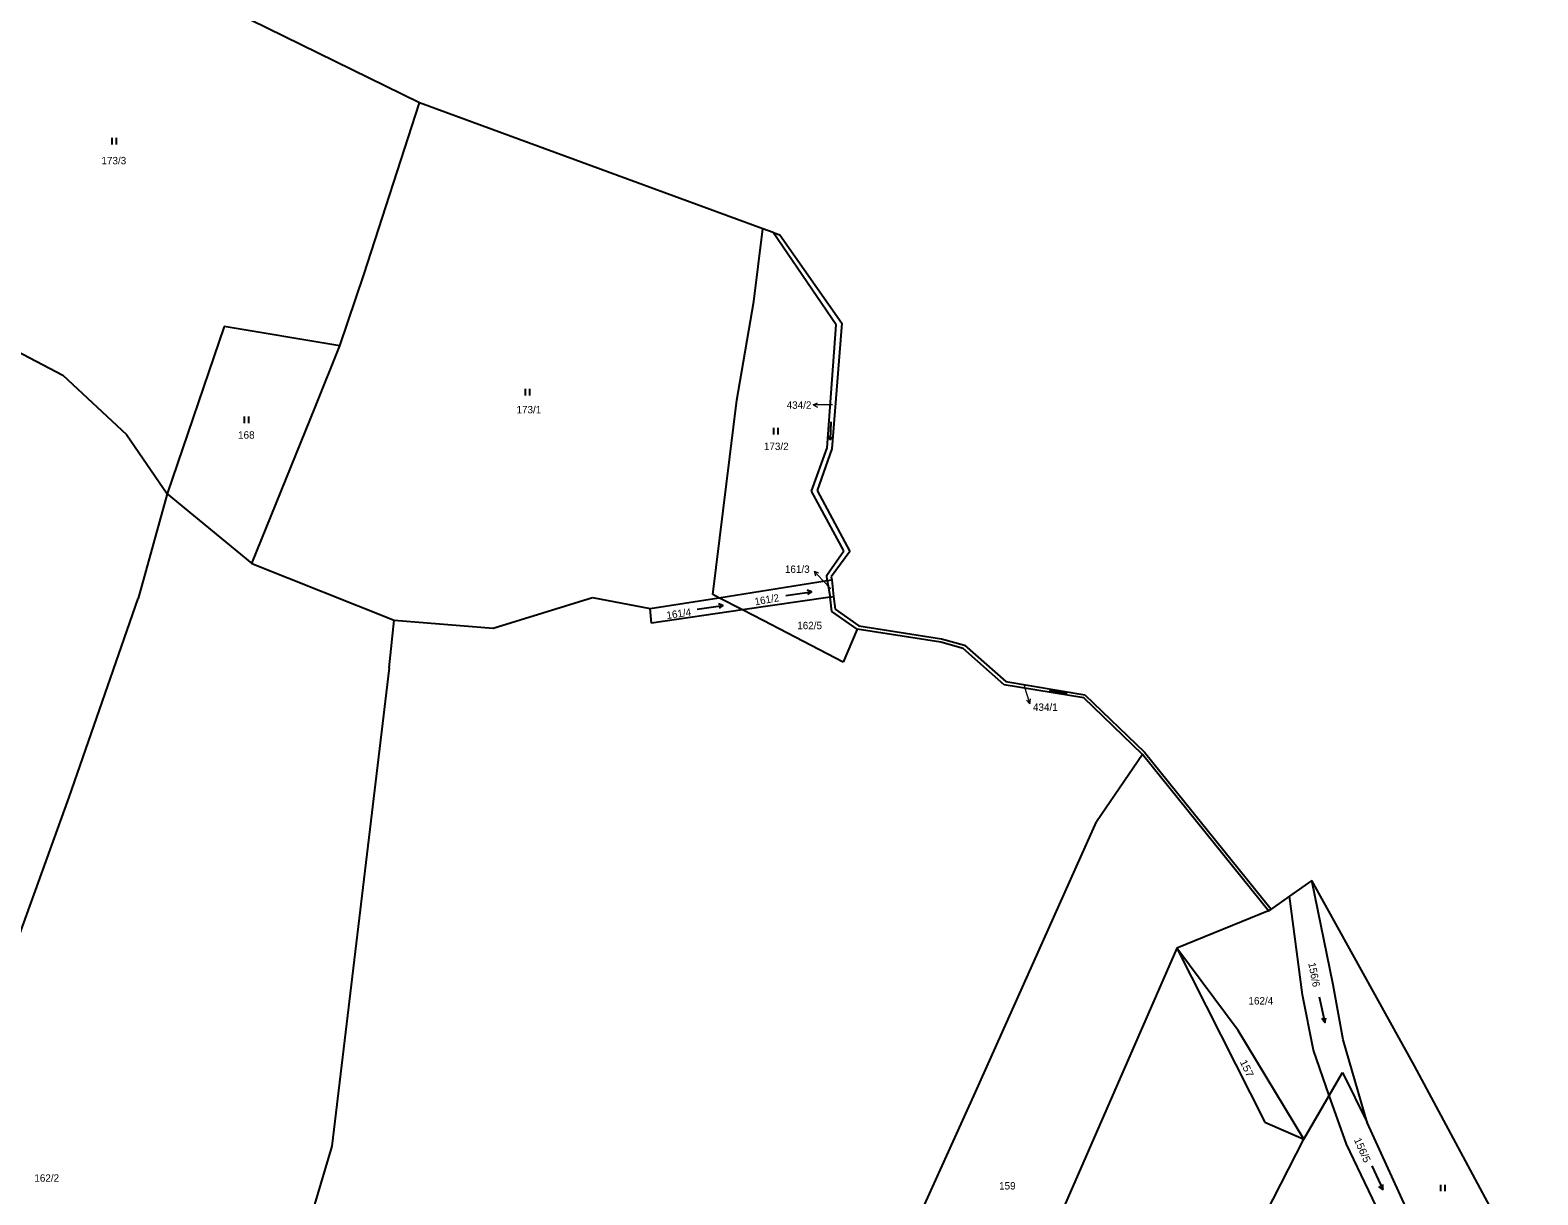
# Model space of a CAD drawing. Extents: x -791548 to -789311, y -1142631 to -1140855.
# Drawn here: x -790140.3 to -789793.9, y -1141655.6 to -1141388.1 of the extents above; entities that cross this region are included whole.
import ezdxf
from ezdxf.enums import TextEntityAlignment as Align

# ---------------------------------------------------------------- set-up
doc = ezdxf.new("R2010")
doc.units = 0
doc.header["$LTSCALE"] = 0.68
for name, color, linetype, lineweight in [('1', 7, 'Continuous', 25), ('3', 7, 'Continuous', 25), ('7', 7, 'Continuous', 13)]:
    doc.layers.add(name, color=color, linetype=linetype, lineweight=lineweight)
doc.layers.add('2', color=7, linetype='Continuous')

msp = doc.modelspace()

# ---------------------------------------------------------------- linework, layer by layer
at = {"layer": '1'}
for p, q in [((-790050.91, -1141404.77), (-790097.47, -1141381.98)), ((-790063.68, -1141444.29), (-790050.91, -1141404.77)), ((-789972, -1141433.72), (-790050.91, -1141404.77)), ((-789974.08, -1141450.41), (-789972, -1141433.72)), ((-789969.65, -1141434.59), (-789972, -1141433.72)), ((-789969.65, -1141434.59), (-789968.14, -1141435.11)), ((-789955.16, -1141455.79), (-789969.65, -1141434.59)), ((-789968.14, -1141435.11), (-789953.89, -1141455.4)), ((-790069.2, -1141460.63), (-790063.68, -1141444.29)), ((-789977.98, -1141473.06), (-789974.08, -1141450.41)), ((-790154.9, -1141455.81), (-790132.85, -1141467.37)), ((-790095.79, -1141456.13), (-790108.83, -1141494.58)), ((-790069.2, -1141460.63), (-790095.79, -1141456.13)), ((-789957.25, -1141484.05), (-789955.16, -1141455.79)), ((-789953.89, -1141455.4), (-789956.14, -1141484.29)), ((-790074.81, -1141474.52), (-790069.2, -1141460.63)), ((-790132.85, -1141467.37), (-790118.23, -1141480.98)), ((-790089.42, -1141510.57), (-790074.81, -1141474.52)), ((-789983.5, -1141517.74), (-789977.98, -1141473.06)), ((-790118.23, -1141480.98), (-790108.83, -1141494.58)), ((-789960.79, -1141493.95), (-789957.25, -1141484.05)), ((-789956.14, -1141484.29), (-789959.54, -1141493.85)), ((-790108.83, -1141494.58), (-790115.53, -1141518.63)), ((-790108.83, -1141494.58), (-790089.42, -1141510.57)), ((-789953.37, -1141507.66), (-789960.79, -1141493.95)), ((-789959.54, -1141493.85), (-789952.02, -1141507.86)), ((-789957.33, -1141513.28), (-789953.37, -1141507.66)), ((-789952.02, -1141507.86), (-789956.28, -1141513.62)), ((-790089.42, -1141510.57), (-790056.74, -1141523.64)), ((-789982.13, -1141518.45), (-789957.23, -1141514.48)), ((-789957.23, -1141514.48), (-789957.33, -1141513.28)), ((-789957.23, -1141514.48), (-789956.19, -1141514.36)), ((-789957.23, -1141514.48), (-789956.56, -1141518.29)), ((-789956.28, -1141513.62), (-789956.19, -1141514.36)), ((-789956.19, -1141514.36), (-789955.74, -1141518.19)), ((-790131.39, -1141564.28), (-790115.53, -1141518.63)), ((-790033.97, -1141525.47), (-790011.18, -1141518.43)), ((-790011.18, -1141518.43), (-789997.91, -1141520.96)), ((-789997.91, -1141520.96), (-789982.13, -1141518.45)), ((-789982.13, -1141518.45), (-789983.5, -1141517.74)), ((-789976.68, -1141521.25), (-789982.13, -1141518.45)), ((-789956.56, -1141518.29), (-789976.68, -1141521.25)), ((-789956.56, -1141518.29), (-789955.74, -1141518.19)), ((-789956.14, -1141521.59), (-789956.56, -1141518.29)), ((-789955.74, -1141518.19), (-789955.4, -1141521.08)), ((-789997.6, -1141524.33), (-789997.91, -1141520.96)), ((-789976.68, -1141521.25), (-789997.6, -1141524.33)), ((-789971.93, -1141523.7), (-789976.68, -1141521.25)), ((-789950.34, -1141525.7), (-789956.14, -1141521.59)), ((-789955.4, -1141521.08), (-789949.94, -1141524.94)), ((-790057.89, -1141534.57), (-790056.74, -1141523.64)), ((-790056.74, -1141523.64), (-790033.97, -1141525.47)), ((-789953.57, -1141533.22), (-789971.93, -1141523.7)), ((-789950.34, -1141525.7), (-789953.57, -1141533.22)), ((-789931.15, -1141528.68), (-789950.34, -1141525.7)), ((-789949.94, -1141524.94), (-789930.99, -1141527.92)), ((-789925.97, -1141530.12), (-789931.15, -1141528.68)), ((-789930.99, -1141527.92), (-789925.71, -1141529.34)), ((-789916.53, -1141538.47), (-789925.97, -1141530.12)), ((-789925.71, -1141529.34), (-789916.16, -1141537.7)), ((-790057.89, -1141534.57), (-790071.03, -1141644.44)), ((-789898.26, -1141541.44), (-789916.53, -1141538.47)), ((-789916.16, -1141537.7), (-789898.04, -1141540.72)), ((-789898.04, -1141540.72), (-789884.3, -1141553.9)), ((-789884.81, -1141554.45), (-789898.26, -1141541.44)), ((-789884.81, -1141554.45), (-789895.37, -1141569.95)), ((-789855.85, -1141590.39), (-789884.81, -1141554.45)), ((-789884.3, -1141553.9), (-789855.24, -1141589.98)), ((-790150.16, -1141616.16), (-790131.39, -1141564.28)), ((-789923.15, -1141632.03), (-789895.37, -1141569.95)), ((-789845.84, -1141583.41), (-789851, -1141587.01)), ((-789822.32, -1141625.96), (-789845.84, -1141583.41)), ((-789841.01, -1141607.39), (-789845.84, -1141583.41)), ((-789851, -1141587.01), (-789854.65, -1141589.57)), ((-789847.99, -1141609.64), (-789851, -1141587.01)), ((-789855.85, -1141590.39), (-789876.88, -1141598.96)), ((-789855.85, -1141590.39), (-789855.24, -1141589.98)), ((-789854.65, -1141589.57), (-789855.24, -1141589.98)), ((-789876.88, -1141598.96), (-789904.34, -1141661.73)), ((-789862.79, -1141617.87), (-789876.88, -1141598.96)), ((-789876.88, -1141598.96), (-789856.66, -1141638.91)), ((-789845.53, -1141622.34), (-789847.99, -1141609.64)), ((-789838.65, -1141619.95), (-789841.01, -1141607.39)), ((-789847.74, -1141642.81), (-789862.79, -1141617.87)), ((-789833.19, -1141638.97), (-789838.65, -1141619.95)), ((-789841.86, -1141632.75), (-789845.53, -1141622.34)), ((-789793.95, -1141678.61), (-789822.32, -1141625.96)), ((-789841.86, -1141632.75), (-789838.8, -1141627.51)), ((-789838.8, -1141627.51), (-789833.19, -1141638.97)), ((-789962.05, -1141717.9), (-789923.15, -1141632.03)), ((-789847.74, -1141642.81), (-789841.86, -1141632.75)), ((-789837.93, -1141643.93), (-789841.86, -1141632.75)), ((-789856.66, -1141638.91), (-789847.74, -1141642.81)), ((-789822.67, -1141661.95), (-789833.19, -1141638.97)), ((-790071.03, -1141644.44), (-790093.8, -1141721.11)), ((-789865.8, -1141678.13), (-789847.74, -1141642.81)), ((-789827.45, -1141665.72), (-789837.93, -1141643.93))]:
    msp.add_line(p, q, dxfattribs=at)
at = {"layer": '3'}
for p, q in [((-790121.491, -1141414.36), (-790121.491, -1141412.86)), ((-790120.49, -1141414.36), (-790120.49, -1141412.86)), ((-790026.511, -1141471.98), (-790026.511, -1141470.48)), ((-790025.51, -1141471.98), (-790025.51, -1141470.48)), ((-790091.111, -1141478.34), (-790091.111, -1141476.84)), ((-790090.11, -1141478.34), (-790090.11, -1141476.84)), ((-789969.501, -1141480.94), (-789969.501, -1141479.44)), ((-789968.5, -1141480.94), (-789968.5, -1141479.44)), ((-789956.562, -1141482.108), (-789956.863, -1141481.437)), ((-789960.811, -1141517.079), (-789961.709, -1141517.711)), ((-789981.161, -1141520.249), (-789982.059, -1141520.881)), ((-789902.27, -1141540.447), (-789902.973, -1141540.664)), ((-789842.921, -1141615.973), (-789843.615, -1141615.121)), ((-789829.593, -1141654.338), (-789830.46, -1141653.664)), ((-789816.241, -1141654.76), (-789816.241, -1141653.26)), ((-789815.24, -1141654.76), (-789815.24, -1141653.26))]:
    msp.add_line(p, q, dxfattribs=at)
for points in [[(-789956.351, -1141478.094), (-789956.562, -1141482.108), (-789956.192, -1141481.472)], [(-789987.103, -1141521.084), (-789981.161, -1141520.249), (-789982.198, -1141519.888)], [(-789966.753, -1141517.914), (-789960.811, -1141517.079), (-789961.848, -1141516.718)], [(-789906.229, -1141539.749), (-789902.27, -1141540.447), (-789902.857, -1141540.002)], [(-789844.169, -1141610.104), (-789842.921, -1141615.973), (-789842.634, -1141614.913)], [(-789832.128, -1141648.9), (-789829.593, -1141654.338), (-789829.551, -1141653.241)]]:
    msp.add_lwpolyline(points, dxfattribs=at)
at = {"layer": '7'}
for p, q in [((-789960.441, -1141474.19), (-789959.44, -1141474.691)), ((-789960.247, -1141512.315), (-789959.93, -1141513.389)), ((-789910.643, -1141542.814), (-789910.476, -1141541.707))]:
    msp.add_line(p, q, dxfattribs=at)
for points in [[(-789956, -1141474.19), (-789957.44, -1141474.19), (-789960.441, -1141474.19), (-789959.44, -1141473.689)], [(-789956.39, -1141516.44), (-789958.2, -1141514.51), (-789960.247, -1141512.315), (-789959.197, -1141512.706)], [(-789912, -1141538.62), (-789911.57, -1141539.96), (-789910.643, -1141542.814), (-789911.428, -1141542.016)]]:
    msp.add_lwpolyline(points, dxfattribs=at)

# ---------------------------------------------------------------- texts
at = {"layer": '2'}
for s, p in [('173/3', (-790121.12, -1141418.912)), ('173/1', (-790025.76, -1141476.102)), ('168', (-790090.679, -1141481.922)), ('173/2', (-789968.92, -1141484.532)), ('162/5', (-789961.26, -1141525.682)), ('162/4', (-789857.59, -1141611.872)), ('162/2', (-790136.53, -1141652.572)), ('159', (-789915.829, -1141654.362))]:
    msp.add_text(s, height=1.7, dxfattribs=at).set_placement(p, align=Align.CENTER)
for s, p in [('434/2', (-789960.85, -1141475.065)), ('161/3', (-789961.25, -1141512.745))]:
    msp.add_text(s, height=1.7, dxfattribs=at).set_placement(p, align=Align.RIGHT)
for s, rotation, p in [('161/2', 10, (-789970.9416, -1141519.7292)), ('161/4', 8, (-789991.2003, -1141522.9508)), ('156/6', 281, (-789846.1627, -1141605.1868))]:
    msp.add_text(s, height=1.7, rotation=rotation, dxfattribs=at).set_placement(p, align=Align.CENTER)
msp.add_text('434/1', height=1.7, dxfattribs=at).set_placement((-789909.95, -1141544.435))
for s, rotation, width, p in [('157', 296, 1.1, (-789861.5695, -1141626.9114)), ('156/5', 294, 1.05, (-789835.0389, -1141645.6483))]:
    msp.add_text(s, height=1.7, rotation=rotation, dxfattribs=dict(at, width=width)).set_placement(p, align=Align.CENTER)

doc.saveas('drawing.dxf')
